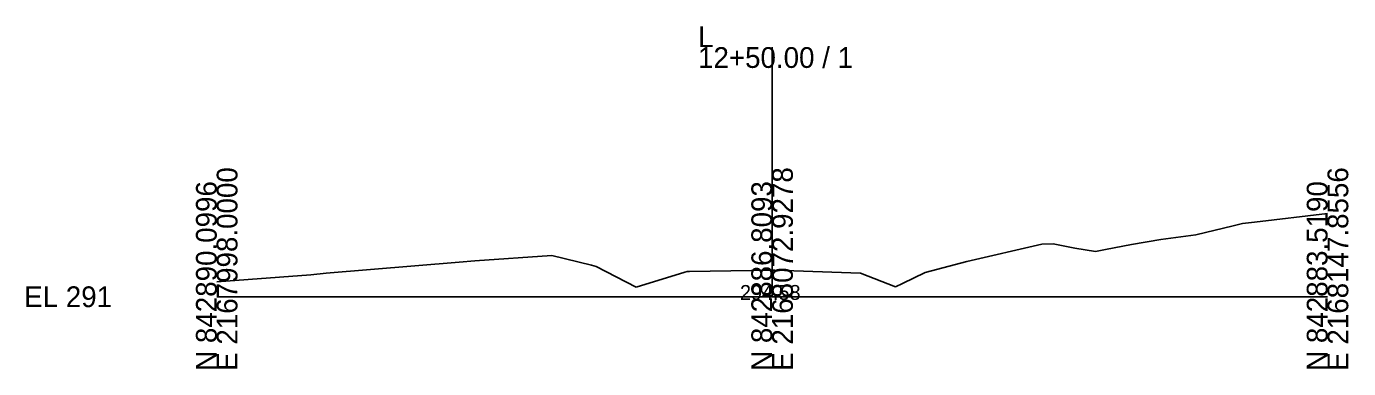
# Model space of a CAD drawing. Extents: x -26 to 1153, y -10 to 9544.
# Drawn here: x -25.7 to 152.8, y -9.7 to 36.5 of the extents above; entities that cross this region are included whole.
import ezdxf

# ---------------------------------------------------------------- set-up
doc = ezdxf.new("R2010")
doc.units = 0
for name, color, linetype in [('Default', 7, 'Continuous'), ('Exist Cross Section Cell', 7, 'Continuous'), ('Exist XS Center Line Elevation Label', 7, 'Continuous'), ('Prop XS Earthwork Shape', 7, 'Continuous')]:
    doc.layers.add(name, color=color, linetype=linetype)

msp = doc.modelspace()

# ---------------------------------------------------------------- linework, layer by layer
at = {"layer": 'Exist Cross Section Cell'}
for p, q in [((75, 0), (75, 33.69)), ((0, 0), (75, 0)), ((75, 0), (150, 0))]:
    msp.add_line(p, q, dxfattribs=at)
at = {"layer": 'Prop XS Earthwork Shape'}
for p, q in [((140.16, 10.05), (150, 11.23)), ((132.2, 8.37), (137.25, 9.59)), ((137.25, 9.59), (138.5, 9.89)), ((138.5, 9.89), (140.16, 10.05)), ((111.4, 7.1), (112.96, 7.16)), ((112.96, 7.16), (115.88, 6.54)), ((123.53, 7.05), (127.47, 7.73)), ((127.47, 7.73), (132.2, 8.37)), ((34.85, 4.83), (45.25, 5.55)), ((45.25, 5.55), (50.6, 4.26)), ((101.31, 4.74), (111.4, 7.1)), ((115.88, 6.54), (118.66, 6.1)), ((118.66, 6.1), (120.02, 6.39)), ((120.02, 6.39), (123.53, 7.05)), ((14.76, 3.18), (32.75, 4.66)), ((32.75, 4.66), (34.85, 4.83)), ((50.6, 4.26), (51.23, 4.07)), ((51.23, 4.07), (56.66, 1.3)), ((63.83, 3.41), (75, 3.58)), ((75, 3.58), (75.38, 3.58)), ((75.38, 3.58), (86.93, 3.19)), ((95.65, 3.26), (101.31, 4.74)), ((0, 2), (12.71, 2.97)), ((12.71, 2.97), (14.76, 3.18)), ((56.66, 1.3), (63.2, 3.32)), ((63.2, 3.32), (63.53, 3.41)), ((63.53, 3.41), (63.83, 3.41)), ((86.93, 3.19), (91.68, 1.35)), ((92.6, 1.77), (95.65, 3.26)), ((91.68, 1.35), (92.6, 1.77))]:
    msp.add_line(p, q, dxfattribs=at)

# ---------------------------------------------------------------- texts
at = {"layer": 'Default'}
msp.add_text('-', height=0.0001, dxfattribs=at).set_placement((0, 0))
at = {"layer": 'Exist Cross Section Cell'}
for s, p in [('L', (65, 33.69)), ('12+50.00 / 1', (65, 30.89)), ('EL 291', (-26, -1.4))]:
    msp.add_text(s, height=2.8, dxfattribs=at).set_placement(p)
for s, p in [('E 2167998.0000', (2.8, -10)), ('E 2168072.9278', (77.8, -10)), ('E 2168147.8556', (152.8, -10)), ('N 842890.0996', (0, -10)), ('N 842886.8093', (75, -10)), ('N 842883.5190', (150, -10))]:
    msp.add_text(s, height=2.8, rotation=90, dxfattribs=at).set_placement(p)
at = {"layer": 'Exist XS Center Line Elevation Label'}
msp.add_text('294.58', height=2, dxfattribs=at).set_placement((70.66, -0.42))

doc.saveas('drawing.dxf')
